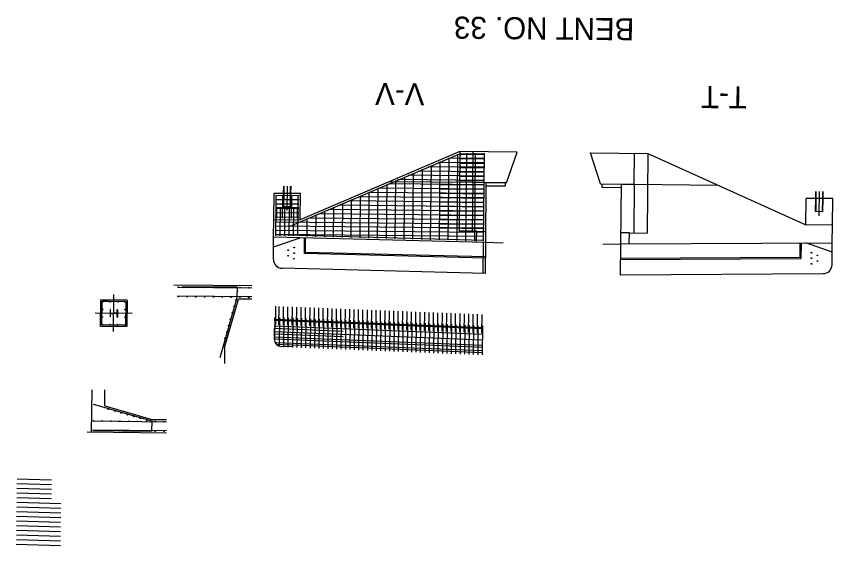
# Model space of a CAD drawing. Extents: x 631918 to 632319, y 373181 to 373282.
# Drawn here: x 632013.2 to 632105.7, y 373191.9 to 373251.9 of the extents above; entities that cross this region are included whole.
import ezdxf

# ---------------------------------------------------------------- set-up
doc = ezdxf.new("R2010")
doc.units = 0
for name, color, linetype in [('B_Boring', 7, 'Continuous'), ('BD-EXIST-OSB', 7, 'Continuous'), ('BD-LEGEND', 7, 'Continuous'), ('BD-PROP-COSS', 7, 'Continuous'), ('BD-REMOVE', 7, 'Continuous'), ('R_Border_Scale', 7, 'Continuous'), ('R_Road Edge of Travel', 7, 'Continuous'), ('R_Shade Removal', 7, 'Continuous'), ('R_Wall', 7, 'Continuous')]:
    doc.layers.add(name, color=color, linetype=linetype)

msp = doc.modelspace()

# ---------------------------------------------------------------- linework, layer by layer
at = {"layer": 'B_Boring'}
for p, q in [((632084.738, 373236.403), (632084.649, 373227.381)), ((632083.204, 373232.918), (632083.149, 373227.396)), ((632082.636, 373226.151), (632082.649, 373227.401)), ((632082.649, 373227.401), (632084.649, 373227.381)), ((632045.824, 373225.073), (632045.841, 373226.823)), ((632045.95, 373225.194), (632045.966, 373226.821)), ((632105.628, 373225.2), (632102.639, 373226.266)), ((632045.95, 373225.194), (632045.824, 373225.073)), ((632066.32, 373224.547), (632045.824, 373225.062)), ((632066.321, 373224.67), (632045.95, 373225.183))]:
    msp.add_line(p, q, dxfattribs=at)
at = {"layer": 'BD-EXIST-OSB'}
for p, q in [((632023.817, 373218.717), (632023.809, 373217.863)), ((632023.864, 373218.716), (632023.817, 373218.717)), ((632023.86, 373218.313), (632023.864, 373218.716)), ((632023.856, 373217.862), (632023.809, 373217.863)), ((632023.856, 373217.862), (632023.86, 373218.266)), ((632023.86, 373218.313), (632024.23, 373218.309)), ((632023.86, 373218.266), (632024.229, 373218.262)), ((632024.599, 373218.259), (632024.229, 373218.262)), ((632024.6, 373218.305), (632024.23, 373218.309)), ((632024.595, 373217.855), (632024.599, 373218.259)), ((632024.595, 373217.855), (632024.642, 373217.854)), ((632024.6, 373218.305), (632024.604, 373218.709)), ((632024.604, 373218.709), (632024.651, 373218.709)), ((632024.651, 373218.709), (632024.642, 373217.854))]:
    msp.add_line(p, q, dxfattribs=at)
at = {"layer": 'BD-LEGEND'}
for p, q in [((632039.871, 373221.38), (632031.026, 373221.468)), ((632022.715, 373216.801), (632022.745, 373219.801)), ((632025.744, 373219.771), (632022.745, 373219.801)), ((632025.744, 373219.771), (632025.715, 373216.771)), ((632036.79, 373214.411), (632038.345, 373219.895)), ((632039.856, 373219.88), (632038.345, 373219.895)), ((632025.715, 373216.771), (632022.715, 373216.801)), ((632036.79, 373214.411), (632036.772, 373212.58)), ((632021.723, 373209.619), (632021.675, 373204.789)), ((632023.205, 373207.774), (632023.223, 373209.604)), ((632023.205, 373207.774), (632028.689, 373206.219)), ((632030.201, 373206.204), (632028.689, 373206.219)), ((632030.186, 373204.704), (632021.204, 373204.793))]:
    msp.add_line(p, q, dxfattribs=at)
at = {"layer": 'BD-PROP-COSS'}
for p, q in [((632063.49, 373236.364), (632044.181, 373228.106)), ((632063.187, 373236.325), (632063.089, 373226.547)), ((632066.27, 373236.336), (632063.49, 373236.364)), ((632064.188, 373236.44), (632064.089, 373226.506)), ((632065.188, 373236.43), (632065.089, 373226.496)), ((632066.188, 373236.42), (632066.089, 373226.486)), ((632066.26, 373235.336), (632060.997, 373235.389)), ((632061.178, 373235.466), (632061.09, 373226.598)), ((632062.182, 373235.895), (632062.09, 373226.573)), ((632066.265, 373235.836), (632062.14, 373235.877)), ((632066.264, 373235.753), (632063.515, 373235.78)), ((632066.269, 373236.253), (632063.52, 373236.28)), ((632063.52, 373236.28), (632063.603, 373236.279)), ((632059.169, 373234.607), (632059.09, 373226.65)), ((632066.255, 373234.836), (632059.855, 373234.9)), ((632060.174, 373235.036), (632060.09, 373226.624)), ((632066.254, 373234.753), (632063.505, 373234.78)), ((632066.259, 373235.253), (632063.51, 373235.28)), ((632057.161, 373233.748), (632057.091, 373226.701)), ((632066.245, 373233.836), (632057.57, 373233.923)), ((632058.165, 373234.177), (632058.09, 373226.675)), ((632066.25, 373234.336), (632058.712, 373234.411)), ((632066.245, 373233.753), (632063.495, 373233.78)), ((632066.249, 373234.253), (632063.5, 373234.28)), ((632055.152, 373232.889), (632055.091, 373226.752)), ((632055.371, 373232.982), (632066.236, 373232.874)), ((632056.156, 373233.318), (632056.091, 373226.727)), ((632066.24, 373233.336), (632056.427, 373233.434)), ((632066.235, 373232.791), (632061.235, 373232.841)), ((632066.24, 373233.253), (632063.49, 373233.28)), ((632053.143, 373232.03), (632053.091, 373226.804)), ((632053.112, 373232.016), (632066.226, 373231.886)), ((632054.148, 373232.459), (632054.091, 373226.778)), ((632054.242, 373232.499), (632066.231, 373232.38)), ((632066.225, 373231.802), (632061.225, 373231.852)), ((632066.23, 373232.297), (632061.23, 373232.346)), ((632045.217, 373231.134), (632042.551, 373231.161)), ((632045.222, 373231.593), (632042.555, 373231.619)), ((632042.626, 373230.368), (632042.639, 373231.66)), ((632043.363, 373229.069), (632043.389, 373231.652)), ((632044.363, 373229.059), (632044.389, 373231.642)), ((632045.126, 373230.343), (632045.139, 373231.635)), ((632050.13, 373230.741), (632050.092, 373226.881)), ((632050.853, 373231.05), (632066.216, 373230.897)), ((632051.135, 373231.17), (632051.092, 373226.855)), ((632051.982, 373231.533), (632066.221, 373231.391)), ((632052.139, 373231.6), (632052.092, 373226.829)), ((632066.215, 373230.814), (632061.216, 373230.863)), ((632066.22, 373231.308), (632061.22, 373231.358)), ((632045.208, 373230.134), (632042.541, 373230.161)), ((632045.208, 373230.218), (632042.542, 373230.244)), ((632045.212, 373230.634), (632042.546, 373230.661)), ((632042.594, 373227.077), (632042.626, 373230.285)), ((632042.626, 373230.368), (632042.709, 373230.284)), ((632042.697, 373229.076), (632042.709, 373230.284)), ((632043.094, 373227.072), (632043.126, 373230.28)), ((632043.594, 373227.067), (632043.625, 373230.275)), ((632044.094, 373227.062), (632044.125, 373230.27)), ((632044.594, 373227.057), (632044.625, 373230.265)), ((632045.03, 373229.053), (632045.042, 373230.261)), ((632045.126, 373230.343), (632045.042, 373230.261)), ((632045.094, 373227.052), (632045.125, 373230.26)), ((632048.122, 373229.882), (632048.092, 373226.932)), ((632048.594, 373230.084), (632066.206, 373229.908)), ((632049.126, 373230.311), (632049.092, 373226.906)), ((632049.723, 373230.567), (632066.211, 373230.403)), ((632066.205, 373229.825), (632061.206, 373229.875)), ((632066.21, 373230.319), (632061.211, 373230.369)), ((632045.198, 373229.134), (632042.531, 373229.161)), ((632045.203, 373229.634), (632042.536, 373229.661)), ((632046.113, 373229.023), (632046.093, 373226.983)), ((632046.334, 373229.117), (632066.196, 373228.92)), ((632047.117, 373229.452), (632047.093, 373226.957)), ((632047.464, 373229.6), (632066.201, 373229.414)), ((632066.201, 373229.331), (632061.201, 373229.381)), ((632042.521, 373228.192), (632066.187, 373227.957)), ((632042.526, 373228.661), (632066.192, 373228.426)), ((632066.191, 373228.342), (632061.191, 373228.392)), ((632066.196, 373228.837), (632061.196, 373228.886)), ((632066.173, 373226.551), (632042.511, 373227.158)), ((632042.512, 373227.255), (632066.178, 373227.019)), ((632042.517, 373227.723), (632066.182, 373227.488)), ((632066.186, 373227.874), (632061.186, 373227.923)), ((632039.869, 373221.13), (632031.451, 373221.214)), ((632038.231, 373221.23), (632031.981, 373221.292)), ((632038.219, 373220.063), (632038.231, 373221.23)), ((632022.883, 373216.966), (632022.91, 373219.674)), ((632023.577, 373219.667), (632022.91, 373219.674)), ((632039.859, 373220.13), (632031.441, 373220.214)), ((632036.297, 373213.282), (632038.219, 373220.063)), ((632022.861, 373218.966), (632022.868, 373219.633)), ((632025.576, 373219.606), (632022.868, 373219.633)), ((632025.576, 373219.606), (632025.55, 373216.939)), ((632042.577, 373216.994), (632042.597, 373219.077)), ((632042.931, 373219.064), (632042.91, 373216.98)), ((632043.43, 373219.044), (632043.41, 373216.96)), ((632043.93, 373219.024), (632043.91, 373216.94)), ((632044.43, 373219.004), (632044.409, 373216.921)), ((632044.93, 373218.984), (632044.909, 373216.901)), ((632045.43, 373218.964), (632045.409, 373216.881)), ((632045.93, 373218.944), (632045.909, 373216.861)), ((632046.429, 373218.924), (632046.409, 373216.841)), ((632046.929, 373218.904), (632046.909, 373216.821)), ((632047.429, 373218.884), (632047.408, 373216.801)), ((632047.929, 373218.864), (632047.908, 373216.781)), ((632048.429, 373218.844), (632048.408, 373216.761)), ((632048.929, 373218.824), (632048.908, 373216.741)), ((632049.428, 373218.804), (632049.408, 373216.721)), ((632049.928, 373218.784), (632049.908, 373216.701)), ((632050.428, 373218.764), (632050.407, 373216.681)), ((632050.928, 373218.744), (632050.907, 373216.661)), ((632051.428, 373218.724), (632051.407, 373216.641)), ((632042.476, 373215.247), (632042.502, 373217.83)), ((632043.002, 373217.81), (632042.969, 373214.561)), ((632043.501, 373217.79), (632043.468, 373214.457)), ((632051.928, 373218.704), (632051.907, 373216.621)), ((632052.427, 373218.684), (632052.407, 373216.601)), ((632052.927, 373218.664), (632052.906, 373216.581)), ((632053.427, 373218.644), (632053.406, 373216.561)), ((632053.927, 373218.624), (632053.906, 373216.541)), ((632054.427, 373218.604), (632054.406, 373216.521)), ((632054.926, 373218.584), (632054.906, 373216.501)), ((632055.426, 373218.564), (632055.406, 373216.481)), ((632055.926, 373218.544), (632055.905, 373216.461)), ((632056.426, 373218.524), (632056.405, 373216.441)), ((632056.926, 373218.504), (632056.905, 373216.421)), ((632057.426, 373218.485), (632057.405, 373216.401)), ((632057.925, 373218.465), (632057.905, 373216.381)), ((632058.425, 373218.445), (632058.405, 373216.361)), ((632058.925, 373218.425), (632058.904, 373216.341)), ((632059.425, 373218.405), (632059.404, 373216.321)), ((632059.925, 373218.385), (632059.904, 373216.301)), ((632060.425, 373218.365), (632060.404, 373216.281)), ((632060.924, 373218.345), (632060.904, 373216.262)), ((632061.424, 373218.325), (632061.404, 373216.242)), ((632061.924, 373218.305), (632061.903, 373216.222)), ((632062.424, 373218.285), (632062.403, 373216.202)), ((632062.924, 373218.265), (632062.903, 373216.182)), ((632063.424, 373218.245), (632063.403, 373216.162)), ((632063.923, 373218.225), (632063.903, 373216.142)), ((632064.423, 373218.205), (632064.402, 373216.122)), ((632064.923, 373218.185), (632064.902, 373216.102)), ((632065.423, 373218.165), (632065.402, 373216.082)), ((632065.923, 373218.145), (632065.902, 373216.062)), ((632025.55, 373216.939), (632022.883, 373216.966)), ((632066.073, 373216.513), (632042.415, 373217.459)), ((632066.074, 373216.638), (632042.416, 373217.584)), ((632044.001, 373217.77), (632043.968, 373214.437)), ((632044.501, 373217.75), (632044.468, 373214.417)), ((632045.001, 373217.731), (632044.968, 373214.397)), ((632045.501, 373217.711), (632045.468, 373214.377)), ((632046, 373217.691), (632045.967, 373214.357)), ((632046.5, 373217.671), (632046.467, 373214.337)), ((632047, 373217.651), (632046.967, 373214.317)), ((632047.5, 373217.631), (632047.467, 373214.297)), ((632048, 373217.611), (632047.967, 373214.278)), ((632048.5, 373217.591), (632048.466, 373214.258)), ((632048.999, 373217.571), (632048.966, 373214.238)), ((632049.499, 373217.551), (632049.466, 373214.218)), ((632049.999, 373217.531), (632049.966, 373214.198)), ((632050.499, 373217.511), (632050.466, 373214.178)), ((632050.999, 373217.491), (632050.966, 373214.158)), ((632051.499, 373217.471), (632051.465, 373214.138)), ((632051.998, 373217.451), (632051.965, 373214.118)), ((632052.498, 373217.431), (632052.465, 373214.098)), ((632052.998, 373217.411), (632052.965, 373214.078)), ((632053.498, 373217.391), (632053.465, 373214.058)), ((632053.998, 373217.371), (632053.965, 373214.038)), ((632054.498, 373217.351), (632054.464, 373214.018)), ((632054.997, 373217.331), (632054.964, 373213.998)), ((632055.497, 373217.311), (632055.464, 373213.978)), ((632055.997, 373217.291), (632055.964, 373213.958)), ((632056.497, 373217.271), (632056.464, 373213.938)), ((632056.997, 373217.251), (632056.964, 373213.918)), ((632057.497, 373217.231), (632057.463, 373213.898)), ((632057.996, 373217.211), (632057.963, 373213.878)), ((632058.496, 373217.191), (632058.463, 373213.858)), ((632058.996, 373217.171), (632058.963, 373213.838)), ((632059.496, 373217.151), (632059.463, 373213.818)), ((632059.996, 373217.131), (632059.962, 373213.798)), ((632060.495, 373217.111), (632060.462, 373213.778)), ((632060.995, 373217.091), (632060.962, 373213.758)), ((632061.495, 373217.072), (632061.462, 373213.738)), ((632061.995, 373217.052), (632061.962, 373213.718)), ((632062.495, 373217.032), (632062.462, 373213.698)), ((632062.995, 373217.012), (632062.961, 373213.678)), ((632063.494, 373216.992), (632063.461, 373213.658)), ((632063.994, 373216.972), (632063.961, 373213.638)), ((632064.494, 373216.952), (632064.461, 373213.619)), ((632064.994, 373216.932), (632064.961, 373213.599)), ((632065.494, 373216.912), (632065.461, 373213.579)), ((632065.994, 373216.892), (632065.96, 373213.559)), ((632066.06, 373215.222), (632042.402, 373216.167)), ((632050.236, 373216.229), (632042.406, 373216.542)), ((632066.067, 373215.888), (632042.408, 373216.834)), ((632042.435, 373215.309), (632042.447, 373216.559)), ((632066.052, 373214.389), (632042.394, 373215.334)), ((632066.054, 373214.639), (632042.396, 373215.584)), ((632050.23, 373215.604), (632042.399, 373215.917)), ((632066.046, 373213.805), (632042.609, 373214.742)), ((632066.048, 373214.014), (632042.617, 373214.95)), ((632044.444, 373214.46), (632043.195, 373214.51)), ((632021.873, 373207.978), (632028.521, 373206.093)), ((632030.199, 373205.954), (632021.854, 373206.037)), ((632028.521, 373206.093), (632028.509, 373204.887)), ((632028.509, 373204.887), (632021.843, 373204.954)), ((632030.189, 373204.954), (632021.844, 373205.037)), ((632017.174, 373199.349), (632013.26, 373199.466)), ((632017.164, 373198.295), (632013.249, 373198.412)), ((632017.169, 373198.822), (632013.254, 373198.939)), ((632017.159, 373197.768), (632013.244, 373197.885)), ((632018.229, 373196.681), (632013.231, 373196.831)), ((632017.151, 373197.24), (632013.236, 373197.358)), ((632018.218, 373195.626), (632013.22, 373195.776)), ((632018.223, 373196.154), (632013.226, 373196.303)), ((632018.208, 373194.572), (632013.21, 373194.722)), ((632018.213, 373195.099), (632013.215, 373195.249)), ((632018.202, 373194.045), (632013.205, 373194.195)), ((632018.192, 373192.991), (632013.194, 373193.14)), ((632018.197, 373193.518), (632013.199, 373193.667)), ((632018.181, 373191.936), (632013.184, 373192.086)), ((632018.187, 373192.463), (632013.189, 373192.613))]:
    msp.add_line(p, q, dxfattribs=at)
for centre, radius in [((632031.535, 373221.255), 0.0417), ((632032.535, 373221.245), 0.0417), ((632033.535, 373221.235), 0.0417), ((632034.535, 373221.225), 0.0417), ((632035.535, 373221.215), 0.0417), ((632036.535, 373221.205), 0.0417), ((632037.535, 373221.195), 0.0417), ((632038.535, 373221.185), 0.0417), ((632039.535, 373221.175), 0.0417), ((632031.524, 373220.172), 0.0417), ((632032.524, 373220.162), 0.0417), ((632033.524, 373220.152), 0.0417), ((632034.524, 373220.142), 0.0417), ((632035.524, 373220.132), 0.0417), ((632036.524, 373220.122), 0.0417), ((632037.524, 373220.112), 0.0417), ((632038.078, 373219.771), 0.0556), ((632038.524, 373220.102), 0.0417), ((632039.524, 373220.092), 0.0417), ((632022.942, 373218.729), 0.0417), ((632022.951, 373219.59), 0.0417), ((632023.812, 373219.582), 0.0417), ((632024.673, 373219.573), 0.0417), ((632025.526, 373218.703), 0.0417), ((632025.534, 373219.564), 0.0417), ((632037.875, 373219.052), 0.0556), ((632022.934, 373217.868), 0.0417), ((632025.517, 373217.842), 0.0417), ((632037.671, 373218.333), 0.0556), ((632022.925, 373217.007), 0.0417), ((632023.786, 373216.998), 0.0417), ((632024.647, 373216.99), 0.0417), ((632025.508, 373216.981), 0.0417), ((632037.263, 373216.894), 0.0556), ((632037.467, 373217.613), 0.0556), ((632037.059, 373216.174), 0.0556), ((632036.855, 373215.455), 0.0556), ((632023.623, 373207.418), 0.0556), ((632024.345, 373207.214), 0.0556), ((632025.067, 373207.009), 0.0556), ((632025.789, 373206.805), 0.0556), ((632021.923, 373206.078), 0.0417), ((632022.923, 373206.068), 0.0417), ((632023.923, 373206.058), 0.0417), ((632024.923, 373206.048), 0.0417), ((632025.923, 373206.038), 0.0417), ((632026.511, 373206.6), 0.0556), ((632026.923, 373206.028), 0.0417), ((632027.233, 373206.395), 0.0556), ((632027.923, 373206.018), 0.0417), ((632027.955, 373206.191), 0.0556), ((632028.923, 373206.008), 0.0417), ((632029.923, 373205.998), 0.0417), ((632021.912, 373204.995), 0.0417), ((632022.912, 373204.985), 0.0417), ((632023.912, 373204.975), 0.0417), ((632024.912, 373204.965), 0.0417), ((632025.912, 373204.955), 0.0417), ((632026.912, 373204.945), 0.0417), ((632027.912, 373204.935), 0.0417), ((632028.912, 373204.925), 0.0417), ((632029.912, 373204.915), 0.0417)]:
    msp.add_circle(centre, radius, dxfattribs=at)
msp.add_arc((632043.227, 373215.301), 0.792, 179.43036, 267.712, dxfattribs=at)
at = {"layer": 'R_Border_Scale'}
for p, q in [((632064.905, 373233.1), (632064.939, 373236.599)), ((632083.204, 373232.918), (632083.239, 373236.418)), ((632064.905, 373233.1), (632055.442, 373233.194)), ((632066.405, 373233.085), (632064.905, 373233.1)), ((632081.704, 373232.933), (632083.204, 373232.918)), ((632083.204, 373232.918), (632092.667, 373232.824)), ((632065.35, 373227.573), (632066.35, 373227.563)), ((632082.649, 373227.401), (632081.649, 373227.411)), ((632066.337, 373226.297), (632042.342, 373226.913)), ((632081.636, 373226.145), (632105.639, 373226.283))]:
    msp.add_line(p, q, dxfattribs=at)
at = {"layer": 'R_Road Edge of Travel'}
for p, q in [((632043.475, 373231.902), (632043.483, 373232.705)), ((632043.522, 373231.901), (632043.53, 373232.705)), ((632044.261, 373231.894), (632044.269, 373232.697)), ((632044.308, 373231.893), (632044.316, 373232.697)), ((632043.46, 373230.402), (632043.475, 373231.902)), ((632043.507, 373230.401), (632043.522, 373231.901)), ((632044.246, 373230.394), (632044.261, 373231.894)), ((632044.293, 373230.393), (632044.308, 373231.893)), ((632103.772, 373231.302), (632103.78, 373232.106)), ((632103.819, 373231.302), (632103.827, 373232.105)), ((632104.558, 373231.294), (632104.566, 373232.098)), ((632104.605, 373231.294), (632104.613, 373232.097)), ((632103.757, 373229.802), (632103.772, 373231.302)), ((632103.804, 373229.802), (632103.819, 373231.302)), ((632104.544, 373229.794), (632104.558, 373231.294)), ((632104.59, 373229.794), (632104.605, 373231.294)), ((632043.46, 373230.402), (632044.293, 373230.393)), ((632104.59, 373229.794), (632103.757, 373229.802))]:
    msp.add_line(p, q, dxfattribs=at)
at = {"layer": 'R_Shade Removal'}
for p, q in [((632063.439, 373236.614), (632045.362, 373228.883)), ((632063.439, 373236.614), (632063.35, 373227.593)), ((632069.939, 373236.55), (632063.439, 373236.614)), ((632068.738, 373233.062), (632069.939, 373236.55)), ((632078.239, 373236.467), (632084.738, 373236.403)), ((632079.371, 373232.956), (632078.239, 373236.467)), ((632084.738, 373236.403), (632102.659, 373228.313)), ((632064.905, 373233.1), (632064.85, 373227.578)), ((632066.405, 373233.085), (632066.337, 373226.297)), ((632068.567, 373232.688), (632066.401, 373232.71)), ((632068.738, 373233.062), (632066.405, 373233.085)), ((632068.571, 373233.063), (632068.567, 373232.688)), ((632079.371, 373232.956), (632081.704, 373232.933)), ((632079.537, 373232.954), (632079.534, 373232.579)), ((632081.704, 373232.933), (632081.636, 373226.145)), ((632042.362, 373228.913), (632042.392, 373231.912)), ((632042.392, 373231.912), (632045.392, 373231.883)), ((632045.362, 373228.883), (632045.392, 373231.883)), ((632079.534, 373232.579), (632081.7, 373232.558)), ((632102.659, 373228.313), (632102.689, 373231.313)), ((632105.689, 373231.283), (632102.689, 373231.313)), ((632105.659, 373228.283), (632105.689, 373231.283)), ((632042.342, 373226.913), (632042.362, 373228.913)), ((632042.362, 373228.913), (632045.362, 373228.883)), ((632105.659, 373228.283), (632102.659, 373228.313)), ((632105.639, 373226.283), (632105.659, 373228.283)), ((632065.35, 373227.573), (632063.35, 373227.593)), ((632065.337, 373226.323), (632065.35, 373227.573)), ((632042.317, 373224.397), (632042.342, 373226.913)), ((632042.331, 373225.829), (632045.341, 373226.836)), ((632066.087, 373226.3), (632066.052, 373222.8)), ((632066.337, 373226.297), (632066.302, 373222.797)), ((632068.336, 373226.246), (632066.337, 373226.297)), ((632079.636, 373226.134), (632081.636, 373226.145)), ((632081.636, 373226.145), (632081.602, 373222.645)), ((632101.997, 373224.636), (632102.014, 373226.264)), ((632102.121, 373224.513), (632102.139, 373226.263)), ((632105.614, 373223.768), (632105.639, 373226.283)), ((632081.619, 373224.395), (632102.121, 373224.503)), ((632081.62, 373224.518), (632101.997, 373224.626)), ((632101.997, 373224.636), (632102.121, 373224.513)), ((632066.302, 373222.797), (632043.291, 373223.388)), ((632081.602, 373222.645), (632104.62, 373222.778))]:
    msp.add_line(p, q, dxfattribs=at)
for centre in [(632043.994, 373225.444), (632044.664, 373225.738), (632103.294, 373225.156), (632043.988, 373224.808), (632044.651, 373224.467), (632044.657, 373225.103), (632103.288, 373224.52), (632103.958, 373224.847), (632103.282, 373223.884), (632103.952, 373224.212)]:
    msp.add_circle(centre, 0.0417, dxfattribs=at)
for centre, start, end in [((632043.317, 373224.387), 179.43036, 268.53089), ((632104.614, 373223.778), 270.32983, 359.43036)]:
    msp.add_arc(centre, 1, start, end, dxfattribs=at)
at = {"layer": 'R_Wall'}
for p, q in [((632043.872, 373229.938), (632043.9, 373232.701)), ((632104.169, 373229.338), (632104.197, 373232.101)), ((632024.209, 373216.2), (632024.251, 373220.4)), ((632026.316, 373218.265), (632022.116, 373218.307))]:
    msp.add_line(p, q, dxfattribs=at)

# ---------------------------------------------------------------- texts
at = {"layer": 'BD-REMOVE'}
for s, p in [('BENT NO. 33', (632083.22, 373251.714)), ('V-V', (632059.435, 373244.358)), ('T-T', (632095.976, 373243.995))]:
    msp.add_text(s, height=2.5, rotation=179.43036, dxfattribs=at).set_placement(p)

doc.saveas('drawing.dxf')
